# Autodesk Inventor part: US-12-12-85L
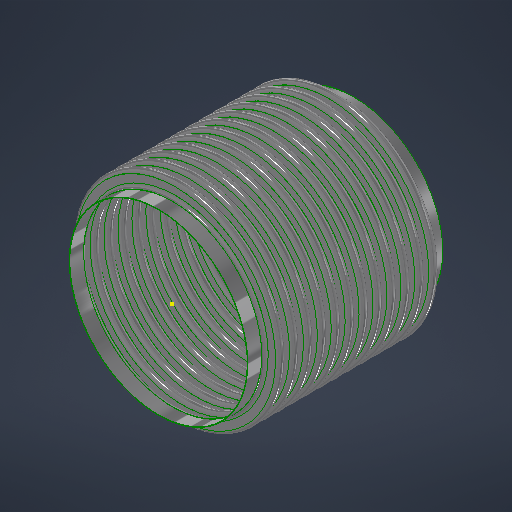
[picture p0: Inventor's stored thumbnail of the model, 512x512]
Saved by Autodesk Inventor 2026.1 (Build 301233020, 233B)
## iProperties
Category: 20 GA (0.036 THICK)
RuleStatus: InUse
Created: 2026-07
Part Number: US-12-12-85L
Project: =STOCK BELLOWS: <Stock Number><SFILL>
Material: ASTM A240-304
Description: =STOCK BELLOWS: <Stock Number>, <SID_> I.D., <SOD_> O.D., <SPLY_> PLY, <Category>, <SNET_CONS> CONS.<PITCH_><STANGENT_> TANGENT<SFILL>
Document SubType Name: Sheet Metal
Designer: LC
Stock Number: U.S-12-12-85L
Surface Area: 659.127 cm^2
Volume: 56.61 cm^3
Sheet Metal Rule: Default
Appearance: STAINLESS STEEL
NET_TUBE: 3.428
COUNTER: 1.500
PBAR: 1.214
PSET: 5.356
PLY: 2
CONS: 2
THK: 0.036
ID: 4.500
OD: 5.500
CONS_: 2
TANGENT: 0.500
PITCH: 0.375
BELLOWS_UPSET: 0.000
NET_CONS: 2
S_CONS: 0
Description_Units: 0
ID_M: 114.30 mm
OD_M: 139.70 mm
THK_M: 0.91 mm
ID_U: 4.500 in
OD_U: 5.500 in
THK_U: 0.036 in
TANGENT2: 0.500
d79: 1.000
d82: 1.000
d83: 26.000
d84: 24.000
d80: 2.571
d81: 10
SID: 2.375
SCONS_: 12
SPITCH: 0.250
SBELLOWS_UPSET: 0.000
SNET_CONS: 12
SS_CONS: 0
SCONS: 8
d174: 8
d177: 0.018
d178: 2.375
d179: 3.000
d180: 0.375
d181: 1.000
d182: 0.000
d190: 8
d191: 1
d192: 1
d193: 8
d194: 0
PART_NUMBER: U.S-12-12-85L
PRESSURE: 85
SIZE: 12.00
STANGENT_: 1.000
d214: 8
d217: 0.030
d218: 6.625
d219: 8.125
d220: 0.500
d221: 1.000
d222: 0.000
d230: 8
d231: 1
d232: 1
d233: 8
d234: 0
STANGENT: 4.000
SPLY_: 1
STHK_: 0.036
SID_: 12.750
SOD_: 14.875
SPITCH_: 1.000
STANGENT__: 1.000
SBELLOWS_UPSET_: 0.000
SDIFF_TAN: 1.000
TAN_TO_TAN: 0.750 in
d252: 2
d275: 2
d287: 0.050
d289: 0.500
d290: 0.000
d263: 2
d265: 1
d268: 2
d269: 0
d286: 2
d288: 1
d291: 2
d292: 0
SOD_NECK: 12 13/16
CFILL: .
SFILL: .
PITCH_: =, <SPITCH_> PITCH,
SREROLL: 0.750
MATTABLE: 20 GA (0.036 THICK)
MESH: ,
CSECT: 2
Author: LC
Keywords: 20 GA (0.036 THICK)
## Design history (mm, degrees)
sketch "Sketch2"
  geometry: L1 (0, -183.595)-(0, 600.956) reference; L2 (58.979, 0)-(57.15, 0); L3 (60.446, -1.467)-(66.554, -1.467); L4 (60.446, -3.296)-(66.554, -3.296); L5 (66.554, -8.058)-(60.446, -8.058); L6 (66.554, -6.229)-(60.446, -6.229); L7 (58.979, -9.525)-(57.15, -9.525); L8 (60.446, 0)-(60.446, -9.525); L9 (66.554, -4.762)-(69.85, -4.763); L10 (57.15, 0)-(57.15, -9.525); L11 (20.376, 102.841)-(20.376, 101.926); L12 (58.262, 488.877)-(58.262, 349.177); L13 (58.262, 479.352)-(58.262, 339.652); L14 (93.133, -58.817)-(93.133, -71.517); L15 (118.746, -66.401)-(118.746, -66.401); L16 (66.554, -6.229)-(66.554, -8.058); L17 (60.446, -6.229)-(60.446, -8.058); L18 (60.446, -7.144)-(66.554, -7.144); L19 (69.85, 0)-(69.85, -9.525); L20 (-66.554, -6.229)-(-66.554, -8.058); L21 (-66.554, -1.467)-(-60.446, -1.467); L22 (-66.554, -3.296)-(-60.446, -3.296); L23 (-60.446, -6.229)-(-66.554, -6.229); L24 (-66.554, -7.144)-(-60.446, -7.144); L25 (-60.446, -8.058)-(-66.554, -8.058); L26 (-60.446, -6.229)-(-60.446, -8.058); L27 (-57.15, -2.522)-(-57.15, -12.047); L28 (-60.446, -4.763)-(-57.15, -4.763); L29 (-66.554, 3.828)-(-66.554, -9.525); L30 (-68.021, 0)-(-69.85, 0); L31 (-69.85, 0)-(-69.85, -9.525); L32 (-68.021, -9.525)-(-69.85, -9.525); A1 r 1.467 centre (60.446, 0) between (58.979, 0) and (60.446, -1.467); A2 r 3.296 centre (60.446, 0) between (57.15, 0) and (60.446, -3.296); A3 r 3.296 centre (66.554, -4.762) between (66.554, -8.058) and (66.554, -1.467); A4 r 1.467 centre (66.554, -4.762) between (66.554, -6.229) and (66.554, -3.296); A5 r 1.467 centre (60.446, -9.525) between (60.446, -8.058) and (58.979, -9.525); A6 r 3.296 centre (60.446, -9.525) between (60.446, -6.229) and (57.15, -9.525); A7 r 2.381 centre (66.554, -4.762) between (66.554, -7.144) and (68.936, -4.762); A8 r 2.381 centre (60.446, -9.525) between (60.446, -7.144) and (58.064, -9.525); A9 r 1.467 centre (-66.554, -9.525) between (-66.554, -8.058) and (-68.021, -9.525); A10 r 1.467 centre (-60.446, -4.763) between (-60.446, -6.229) and (-60.446, -3.296); A11 r 2.381 centre (-60.446, -4.763) between (-60.446, -7.144) and (-58.064, -4.763); A12 r 3.296 centre (-60.446, -4.763) between (-60.446, -8.058) and (-60.446, -1.467); A13 r 2.381 centre (-66.554, -9.525) between (-66.554, -7.144) and (-68.936, -9.525); A14 r 3.296 centre (-66.554, -9.525) between (-66.554, -6.229) and (-69.85, -9.525); A15 r 1.467 centre (-66.554, 0) between (-68.021, 0) and (-66.554, -1.467); A16 r 3.296 centre (-66.554, 0) between (-69.85, 0) and (-66.554, -3.296); 10 further points
  constraints: 62 end point, 38 point on circle, 20 tangent, 16 centre point, 12 parallel, 9 midpoint, 7 vertical, 6 coincident, 6 concentric, 6 point on line, 4 equal radius, 4 perpendicular, 3 horizontal, 1 collinear, 1 horizontal alignment, 10 other
  dimensions: "THK" = 0.9144 distance of L11.start L11.end; "ID" = 114.3 distance of L11.end point (20.376, -12.374); "OD" = 139.7 distance of L12.start L12.end; "PITCH" = 9.525 distance of L12.start L13.start; "TANGENT" = 12.7 distance of L14.start L14.end; "BELLOWS_UPSET" = 0 distance of L15.start L15.end; "d43" = 114.3 diameter of L10 L1 (= ID); "d44" = 139.7 diameter of L9.end L1 (= OD); "d45" = 1.8288 distance between parallel lines of L5 L6 (computed from THK, PLY); "d46" = 3.29565 radius of A3 (computed from PITCH, THK, PLY); "UPSET_PITCH" = 9.525 distance of L2.end L7.end (derived); "SIDEWALL_ANGLE" = 0 deg angle of L3 L9 (derived); "CON_GAP" = 2.9337 distance of point (60.446, -6.229) point (60.446, -3.296) (derived); "TAN1" = 3.74046 dimension on A8 (derived); "TAN2" = 3.74046 dimension on A7 (derived); "LEG1" = 6.1087 distance of L18.start L18.end (derived); "d278" = 1.8288 distance between parallel lines of L25 L23 (derived); "d279" = 3.29565 radius of A12 (derived); "d280" = 9.525 distance of L30.end L31.end (derived); "d281" = 360 deg dimension on L21 L28 (derived); "d282" = 2.9337 distance of point (-66.554, -6.229) point (-66.554, -3.296) (derived); "d283" = 3.74046 dimension on A13 (derived); "d284" = 3.74046 dimension on A11 (derived); "d285" = 6.1087 distance of L24.start L24.end (derived); "d293" = 114.3 diameter of L27 L1 (derived); "d294" = 139.7 diameter of L31 L1 (derived)
  node "Sketch Rectangular Pattern1" dims "d31" = 25.4, "ID" = 114.3
  node "Sketch Rectangular Pattern2" dims "d39" = 25.4, "PITCH" = 9.525
revolve "CONS" stored, may be unused: angle "d48" = 90 deg
node "BELLOW MIDPLANE"
pattern_linear "Rectangular Pattern2" dims "d52" = 9.525 (= UPSET_PITCH)
sketch "Sketch5"
  geometry: C1 r 58.979 at (0, 0) reference; C2 r 57.15 at (0, 0) reference
extrude "TANGENT" new body sketch "Sketch5" distance "d53" = 12.7 (= TANGENT); taper "d54" = 0 deg
revolve "SAMETAN" stored, may be unused: angle "d65" = 90 deg
revolve "DIFFTAN" stored, may be unused: angle "d70" = 90 deg
sketch "Sketch9"
  geometry: L1 (58.391, 0)-(-58.391, 0) reference; L2 (0, -17.78)-(0, 17.78) reference; L3 (41.708, 0)-(-41.708, 0); L4 (41.708, -11.906)-(41.708, 11.906); L5 (29.008, -11.906)-(29.008, 11.906); L6 (15.418, 11.906)-(15.418, -11.906); L7 (-29.008, -11.906)-(-29.008, 11.906); L8 (-41.708, -11.906)-(-41.708, 11.906); L9 (40.914, -11.906)-(40.914, 11.906); L10 (41.708, -11.906)-(40.914, -11.906); L11 (41.708, 11.906)-(40.914, 11.906); L12 (15.815, 11.906)-(15.022, 11.906); L13 (15.022, 11.906)-(15.022, -11.906); L14 (15.022, -11.906)-(15.815, -11.906); L15 (15.815, -11.906)-(15.815, 11.906); L16 (-15.815, 11.906)-(-15.815, -11.906); L17 (-15.418, 11.906)-(-15.418, -11.906); L18 (-15.815, -11.906)-(-15.022, -11.906); L19 (-15.022, -11.906)-(-15.022, 11.906); L20 (-15.022, 11.906)-(-15.815, 11.906); L21 (-41.708, -11.906)-(-40.914, -11.906); L22 (-40.914, -11.906)-(-40.914, 11.906); L23 (-40.914, 11.906)-(-41.708, 11.906); L24 (-41.708, 11.906)-(-41.708, -11.906); L25 (41.708, -0.397)-(-41.708, -0.397); L26 (-41.708, -0.397)-(-41.708, 0.397); L27 (-41.708, 0.397)-(41.708, 0.397); L28 (41.708, 0.397)-(41.708, -0.397); L29 (-41.708, 11.906)-(41.708, 11.906); L30 (41.708, 11.906)-(41.708, 12.7); L31 (41.708, 12.7)-(-41.708, 12.7); L32 (-41.708, 12.7)-(-41.708, 11.906); L33 (41.708, -11.906)-(-41.708, -11.906); L34 (-41.708, -11.906)-(-41.708, -12.7); L35 (-41.708, -12.7)-(41.708, -12.7); L36 (41.708, -12.7)-(41.708, -11.906); 30 further points
  constraints: 68 end point, 13 midpoint, 13 parallel, 8 horizontal, 7 perpendicular, 6 equal length, 3 point on line, 2 vertical, 14 other
  dimensions: "d115" = 23.8125 distance of L4.start L4.end (derived); "d116" = 12.7 distance between parallel lines of L4 L5 (derived); "d117" = 13.58962 distance between parallel lines of L5 L6 (derived); "d125" = 44.42645 distance between parallel lines of L7 L6 (derived); "d127" = 12.7 distance between parallel lines of L8 L7 (derived); "d128" = 26.28962 distance between parallel lines of L6 L4 (derived); "d130" = 83.41607 distance between parallel lines of L8 L4 (derived); "RULER_THK" = 0.79375 distance between parallel lines of L4 L9; "d135" = 0.79375 distance of L13.end L14.end (derived); "d138" = 30.83684 distance of L13.end L16.end (derived); "d143" = 0.79375 distance of L22.end L8.end (derived); "d144" = 0.79375 distance between parallel lines of L27 L25 (derived)
extrude "RULER" join sketch "Sketch9" distance "d149" = 0.79375 (derived); taper "d150" = 0 deg
extrude "BARS" join sketch "Sketch9" distance "d151" = 0.79375 (derived); taper "d152" = 0 deg
pattern_linear "Rectangular Pattern4" dims "d155" = 30.83684 (derived)
sketch "Sketch13"
  geometry: L1 (93.149, -52.467)-(93.149, -77.867); L2 (162.839, 0)-(161.925, 0); L3 (162.839, -25.4)-(161.925, -25.4); L4 (182.105, -19.507)-(168.732, -19.507); L5 (182.105, -18.593)-(168.732, -18.593); L6 (182.105, -12.7)-(188.912, -12.7); L7 (168.732, -5.893)-(182.105, -5.893); L8 (168.732, 0)-(168.732, -25.4); L9 (161.925, 0)-(161.925, -25.4); L10 (58.254, -267.831)-(58.254, -645.656); L11 (58.254, -293.231)-(58.254, -671.056); L12 (58.254, -344.031)-(58.254, -721.856); L13 (58.254, -369.431)-(58.254, -747.256); L14 (58.254, -394.831)-(58.254, -772.656); L15 (58.254, -420.231)-(58.254, -798.056); L16 (58.254, -445.631)-(58.254, -823.456); L17 (58.254, -318.631)-(58.254, -696.456); L18 (20.376, 102.841)-(20.376, 101.926); L19 (168.732, -6.807)-(182.105, -6.807); L20 (0, -960.455)-(0, 280.056) reference; L21 (-31.75, 0)-(190.5, 0) reference; A1 r 5.893 centre (168.732, 0) between (162.839, 0) and (168.732, -5.893); A2 r 5.893 centre (168.732, -25.4) between (168.732, -19.507) and (162.839, -25.4); A3 r 6.807 centre (168.732, -25.4) between (168.732, -18.593) and (161.925, -25.4); A4 r 5.893 centre (182.105, -12.7) between (182.105, -18.593) and (182.105, -6.807); A5 r 6.807 centre (182.105, -12.7) between (182.105, -19.507) and (182.105, -5.893); A6 r 6.807 centre (168.732, 0) between (161.925, 0) and (168.732, -6.807); 6 further points; 1 other entity
  constraints: 38 end point, 15 point on circle, 9 tangent, 6 centre point, 6 parallel, 5 vertical alignment, 4 point on line, 4 vertical, 3 coincident, 3 concentric, 2 collinear, 2 equal radius, 1 horizontal, 1 perpendicular, 23 other
  dimensions: "SBELLOWS_UPSET_" = 0 distance of point (118.762, -66.401) point (118.762, -66.401); "STOTAL_THK_BELLOW__" = 0.9144 distance between parallel lines of L4 L5 (derived); "d224" = 6.8072 radius of A5 (derived); "d225" = 25.4 distance of L2.end L3.end (derived); "SSIDEWALL_ANGLE_" = 0 deg angle of L7 L6 (derived); "SSCON_GAP_" = 11.7856 distance of point (168.732, -18.593) point (168.732, -6.807) (derived); "d235" = 323.85 diameter of L9 L20 (derived); "d236" = 377.825 diameter of L6.end L20 (derived)
  node "Sketch Rectangular Pattern4" dims "d228" = 25.4
  node "Sketch Rectangular Pattern5" dims "d229" = 25.4
revolve "SBELLOW" stored, may be unused: angle "d197" = 90 deg
pattern_linear "Rectangular Pattern5" dims "d204" = 25.4 (derived)
revolve "STANGENT" stored, may be unused: angle "d240" = 90 deg
revolve "SSAMETAN" stored, may be unused: angle "d241" = 90 deg
revolve "SDIFFTAN" stored, may be unused: angle "d246" = 90 deg
revolve "INVCON" stored, may be unused: angle "d295" = 90 deg
pattern_linear "Rectangular Pattern6" dims "d298" = 9.525 (derived)
revolve "INVTANGENT" stored, may be unused: angle "d302" = 90 deg
revolve "INVSAMETAN" stored, may be unused: angle "d307" = 90 deg
revolve "INVDIFFTAN" stored, may be unused: angle "d312" = 90 deg
sketch "ID BELLOW MOUNT CALC"
  geometry: L1 (44.45, 0)-(38.1, 0); L2 (38.1, 0)-(38.1, 12.7); L3 (38.1, 12.7)-(44.45, 12.7); L4 (44.45, 12.7)-(44.45, 0); L5 (36.513, 12.7)-(34.684, 12.7); L6 (34.684, 12.7)-(34.684, 0); L7 (34.684, 0)-(36.513, 0); L8 (36.513, 0)-(36.513, 12.7); L9 (0, -2.54)-(0, 15.24) reference; L10 (-8.89, 0)-(53.34, 0) reference; 1 further point
  constraints: 16 end point, 5 parallel, 2 collinear, 2 horizontal, 2 perpendicular
  dimensions: "d314" = 12.7 distance of L5.end L6.end (derived); "d315" = 1.8288 distance of L5.start L5.end (derived); "IG" = 1.5875 distance between parallel lines of L2 L8; "PIPE_OD" = 88.9 diameter of L4 L9; "PIPE_WALL" = 6.35 distance of L2.end L3.end; "ID_MT_BELLOW" = 69.3674 diameter of L6 L9 (derived)
revolve "CFILL" stored, may be unused: angle "d320" = 90 deg
pattern_linear "Rectangular Pattern7" dims "d323" = 9.525 (derived)
revolve "SFILL" stored, may be unused: angle "d324" = 90 deg
pattern_linear "Rectangular Pattern8" dims "d327" = 25.4 (derived)
node "STOCK BELLOW MIDPLANE"
sketch "Sketch21"
  geometry: L1 (0, -100.013)-(0, 100.013) reference; L2 (-100.013, 0)-(100.013, 0) reference; L3 (-0.099, 71.437)-(0.099, 71.437); L4 (0.099, 71.437)-(0.099, 55.562); L5 (0.099, 55.562)-(-0.099, 55.562); L6 (-0.099, 55.562)-(-0.099, 71.437); C1 r 55.562 at (0, 0); C2 r 71.437 at (0, 0); 3 further points
  constraints: 8 end point, 2 centre point, 2 coincident, 2 parallel, 2 tangent, 1 horizontal, 1 perpendicular, 1 other
  dimensions: "d329" = 111.125 diameter of C1 (derived); "d330" = 142.875 diameter of C2 (derived); "d331" = 0.19844 distance of L3.start L3.end
extrude "CLAMSHELL" cut sketch "Sketch21" extent not by distance; stored distance "d332" = 0; taper "d333" = 0 deg
pattern_circular "Circular Pattern1" dims angle "d335" = 180 deg (derived)
node "BELLOW"
sketch "Sketch6"
  geometry: L1 (-19.05, 58.979)-(-6.35, 58.979); L2 (-6.35, 58.979)-(-6.35, 57.15); L3 (-6.35, 57.15)-(-19.05, 57.15); L4 (-19.05, 57.15)-(-19.05, 58.979); L5 (2.54, 0)-(-59.69, 0) reference; L6 (-38.1, -108.388)-(-38.1, 156.601) reference; 1 further point
  constraints: 8 end point, 2 parallel, 1 horizontal, 1 perpendicular
  dimensions: "d61" = 12.7 distance of L2.end L3.end (derived); "d62" = 1.8288 distance of L1.end L2.end (derived); "d63" = 114.3 diameter of L3 L5 (derived); "d64" = 19.05 distance between parallel lines of L4 L6 (derived)
sketch "Sketch12"
  geometry: 1 further point
sketch "Sketch14"
  geometry: L1 (-25.4, 162.839)-(0, 162.839); L2 (0, 162.839)-(0, 161.925); L3 (0, 161.925)-(-25.4, 161.925); L4 (-25.4, 161.925)-(-25.4, 162.839); L5 (5.08, 0)-(-30.48, 0) reference; L6 (0, -27.488)-(0, 164.927) reference; 1 further point
  constraints: 8 end point, 2 parallel, 1 collinear, 1 horizontal, 1 perpendicular
  dimensions: "d237" = 0.9144 distance of L3.end L1.start (derived); "d238" = 323.85 diameter of L3 L5 (derived); "d239" = 25.4 distance of L1.start L1.end (derived); "SOD_NECK" = 325.6788 diameter of L1 L5 (derived)
sketch "Sketch15"
  geometry: L1 (-27.488, 0)-(164.927, 0) reference; L2 (161.925, -304.8)-(162.839, -304.8); L3 (162.839, -304.8)-(162.839, -330.2); L4 (162.839, -330.2)-(161.925, -330.2); L5 (161.925, -330.2)-(161.925, -304.8); L6 (0, -398.78)-(0, 81.28) reference; 1 further point
  constraints: 8 end point, 2 parallel, 1 horizontal, 1 perpendicular
  dimensions: "d205" = 25.4 distance of L4.end L2.start (derived); "d206" = 0.9144 distance of L3.end L4.end (derived); "d207" = 323.85 diameter of L5 L6 (derived); "d208" = 304.8 distance between parallel lines of L1 L2 (derived)
node "TANGENT_"
node "SAME_TAN"
sketch "Sketch8"
  geometry: L1 (58.979, -19.05)-(57.15, -19.05); L2 (57.15, -19.05)-(57.15, -31.75); L3 (57.15, -31.75)-(58.979, -31.75); L4 (58.979, -31.75)-(58.979, -19.05); L5 (0, -40.64)-(0, 21.59) reference; L6 (-108.388, 0)-(156.601, 0) reference; 1 further point
  constraints: 8 end point, 2 parallel, 1 horizontal, 1 perpendicular
  dimensions: "d66" = 114.3 diameter of L2 L5 (derived); "TOTAL_THK_BELLOW" = 1.8288 distance of L2.end L3.end (derived); "d68" = 19.05 distance between parallel lines of L1 L6 (derived); "d69" = 12.7 distance of L1.end L2.end (derived)
node "DIFF_TAN"
node "Sketch Rectangular Pattern3" dims "d138" = 30.83684 (derived), "d141" = 25.4
node "SBELLOW_"
node "STANGENT_"
node "SSAME_TAN"
sketch "Sketch16"
  geometry: L1 (162.839, -304.8)-(161.925, -304.8); L2 (161.925, -304.8)-(161.925, -330.2); L3 (161.925, -330.2)-(162.839, -330.2); L4 (162.839, -330.2)-(162.839, -304.8); L5 (0, -398.78)-(0, 81.28) reference; L6 (-27.488, 0)-(164.927, 0) reference; 1 further point
  constraints: 8 end point, 2 parallel, 1 horizontal, 1 perpendicular
  dimensions: "SDIFF_TAN" = 25.4 distance of L3.end L1.start; "d243" = 0.9144 distance of L2.end L3.end (derived); "d244" = 304.8 distance between parallel lines of L1 L6 (derived); "d245" = 323.85 diameter of L2 L5 (derived)
node "SDIFF_TAN"
body "Solid15"
sketch "Sketch17"
  geometry: L1 (69.85, 12.7)-(68.021, 12.7); L2 (68.021, 12.7)-(68.021, 0); L3 (68.021, 0)-(69.85, 0); L4 (69.85, 0)-(69.85, 12.7); L5 (0, -2.54)-(0, 15.24) reference; L6 (-13.97, 0)-(83.82, 0) reference; 2 further points
  constraints: 8 end point, 2 parallel, 1 horizontal, 1 midpoint, 1 perpendicular, 1 point on line
  dimensions: "INVTANGENT" = 12.7 distance of L3.end L1.start (derived); "d300" = 1.8288 distance of L1.start L1.end (derived); "d301" = 139.7 diameter of L4 L5 (derived)
body "Solid16"
sketch "Sketch18"
  geometry: L1 (69.85, -19.05)-(68.021, -19.05); L2 (68.021, -19.05)-(68.021, -31.75); L3 (68.021, -31.75)-(69.85, -31.75); L4 (69.85, -31.75)-(69.85, -19.05); L5 (-13.97, 0)-(83.82, 0) reference; L6 (0, -40.64)-(0, 21.59) reference; 1 further point
  constraints: 8 end point, 2 parallel, 1 horizontal, 1 perpendicular
  dimensions: "d303" = 19.05 distance between parallel lines of L1 L5 (derived); "d304" = 12.7 distance of L3.end L1.start (derived); "d305" = 1.8288 distance of L2.end L3.end (derived); "d306" = 139.7 diameter of L4 L6 (derived)
body "Solid17"
sketch "Sketch19"
  geometry: L1 (69.85, -19.05)-(68.021, -19.05); L2 (68.021, -19.05)-(68.021, -31.75); L3 (68.021, -31.75)-(69.85, -31.75); L4 (69.85, -31.75)-(69.85, -19.05); L5 (0, -40.64)-(0, 21.59) reference; L6 (-13.97, 0)-(83.82, 0) reference; 1 further point
  constraints: 8 end point, 2 parallel, 1 horizontal, 1 perpendicular
  dimensions: "d308" = 12.7 distance of L1.end L2.end (derived); "d309" = 139.7 diameter of L4 L5 (derived); "d310" = 1.8288 distance of L2.end L3.end (derived); "d311" = 19.05 distance between parallel lines of L1 L6 (derived)
body "Solid18"
body "Solid19"
body "Solid20"
other parameters: "BMPL" = -152.4, "PSET" = 136.0424 (computed from OD, THK, PLY) [user parameter], "PBAR" = 30.83684 (= 0.570796 x PITCH + OD - ID) [user parameter; used in 1 equation term], "COUNTER" = 15 [user parameter], "NET_TUBE" = 87.07367 (computed from CONS_, PBAR, TANGENT) [user parameter], "S_CONS" = 0 [user parameter; used in 1 equation term], "ID_M" = 114.3 (= ID) [user parameter], "OD_M" = 139.7 (= OD) [user parameter], "THK_M" = 0.9144 (= THK) [user parameter], "ID_U" = 114.3 (= ID) [user parameter], "OD_U" = 139.7 (= OD) [user parameter], "THK_U" = 0.9144 (= THK) [user parameter], "D_UNITS" = 0 [user parameter], "TANGENT2" = 12.7 [user parameter], "TAN_TO_TAN" = 19.05 [user parameter], "OD_NECK" = 117.9576 [user parameter], "d79" = 25.4, "d80" = 65.29823 [user parameter], "d82" = 25.4, "d83" = 660.4, "d84" = 609.6, "sa_0" = 4, "FRAME_THK" = 0.79375 [user parameter], "CON_FLAT" = 13.58962 [user parameter], "SID" = 60.325 [user parameter], "SPITCH" = 6.35 [user parameter], "STANGENT_" = 25.4 [user parameter], "SBELLOWS_UPSET" = 0 [user parameter], "SS_CONS" = 0 [user parameter], "STAN_TO_TAN_" = 304.8 [user parameter], "d100" = 0.9144 [user parameter], "d191" = 25.4 [user parameter], "d194" = 0 [user parameter], "STANGENT" = 101.6 [user parameter], "d234" = 0 [user parameter], "SUPSET_PITCH_" = 25.4 [user parameter], "d269" = 0 [user parameter], "d287" = 1.27, "d289" = 12.7, "d290" = 0, "d292" = 0 [user parameter], "Thickness" = 3.048 (derived), "KFactor" = 4.4, "BendRadius" = 3.048 (derived), "BendReliefWidth" = 3.048 (derived), "BendReliefDepth" = 1.524 (derived), "CornerReliefSize" = 12.192 (derived), "SeamGap" = 0.00508, "MinimumRemnant" = 6.096 (derived), "TransitionRadius" = 3.048 (derived), "JacobiRadiusSize" = 3.048 (derived), "GapSize" = 3.048 (derived), "SREROLL" = 19.05 [user parameter], "CUR_STK_PITCH" = 25.4 [user parameter], "d328" = -152.4 (derived), "CSECTDEG" = 180 deg [user parameter]
